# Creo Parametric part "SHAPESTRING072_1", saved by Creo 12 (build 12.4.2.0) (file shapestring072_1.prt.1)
Units: Custom; MM, KILOGRAM, SECS

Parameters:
  PTC_WM_ITERATION = "0"
  PTC_WM_VERSION = "-.0"
  PTC_WM_LIFECYCLE_STATE = "In Work"
  PTC_WM_LIFECYCLE = "MO_CADDocument"
  PTC_WM_CREATED_BY = "Maximilian Roepper (Z0017RMS: MO)"
  PTC_WM_CREATED_ON = "18-Sep-26 11:36:42 AM"
  PTC_WM_MODIFIED_BY = "Maximilian Roepper (Z0017RMS: MO)"
  PTC_WM_MODIFIED_ON = "18-Sep-26 11:36:46 AM"
  PDMLINKNUMBER = "PDM000071454976"
  PTC_WM_NAME = "shapestring072_1.prt"
  PTC_WM_NUMBER = "PDM000071454976"

Other parameters: WEIGHT, WEIGHT_FACTOR, WEIGHT_ADD, _MASS_TEMP, _DIFF_TEMP, MC_ERRORS, SUPPLIER

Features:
  1. coordinate system
  2. datum plane "PRT_YZ"
  3. datum plane "PRT_XY"
  4. datum plane "PRT_XZ"
  5. coordinate system
  6. datum axis
  7. datum axis
  8. datum axis
  9. coordinate system
  10. imported feature
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
Other named items: PRT, SIEMENS_MO, DRW_VIEW_ORG, PRT_X, PRT_Y, PRT_Z, CS0, ROUGH_GROB

Layers: 00_STD_CSYS-KSYS, 01_STD_PLANES-EBENEN, 02_STD_AXES-ACHSEN, 03_STD_CSYS-KSYS, 24_IMPORT_FEAT-IMPORT_KE, INTFCLR

Surfaces: 1 plane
